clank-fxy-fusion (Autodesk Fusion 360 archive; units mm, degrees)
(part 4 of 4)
sketch "Y Belt Clamp" plane through (-23.5, 0, 0) normal (-1, 0, 0) x axis (0, -1, 0)
  line L1 (-13.5, 0) -> (-42.5, 0)
  line L2 (-13.5, 20) -> (-13.5, 0)
  line L3 (-42.5, 20) -> (-13.5, 20)
  line L4 (-42.5, 0) -> (-42.5, 20)
  line L5 (-37.5, 19.0415) -> (-34, 17.0207)
  line L6 (-41, 17.0207) -> (-37.5, 19.0415)
  line L7 (-41, 12.9793) -> (-41, 17.0207)
  line L8 (-37.5, 10.9585) -> (-41, 12.9793)
  line L9 (-34, 12.9793) -> (-37.5, 10.9585)
  line L10 (-34, 17.0207) -> (-34, 12.9793)
  line L11 (-23, 2.4793) -> (-23, 6.5207)
  line L12 (-16, 6.5207) -> (-16, 2.4793)
  line L13 (-16, 2.4793) -> (-19.5, 0.4585)
  line L14 (-23, 6.5207) -> (-19.5, 8.5415)
  line L15 (-19.5, 0.4585) -> (-23, 2.4793)
  line L16 (-19.5, 8.5415) -> (-16, 6.5207)
  line L17 (-72.1707, -2) -> (34.4892, -2)
  line L18 (-68.7635, -22) -> (35.0352, -22)
  line L19 (-16, -26.3293) -> (-16, -30.3707)
  line L20 (-23, -26.3293) -> (-19.5, -24.3085)
  line L21 (-19.5, -32.3915) -> (-23, -30.3707)
  line L22 (-16, -30.3707) -> (-19.5, -32.3915)
  line L23 (-23, -30.3707) -> (-23, -26.3293)
  line L24 (-19.5, -24.3085) -> (-16, -26.3293)
  line L25 (-19.5, -28.35) -> (-19.5, 4.5)
  line L26 (-25.5, -32.05) -> (-31, -32.05)
  line L27 (-25.5, -24.3085) -> (-25.5, -32.05)
  line L28 (-31, -24.3085) -> (-25.5, -24.3085)
  line L29 (-31, -32.05) -> (-31, -24.3085)
  line L30 (-12.5, -21.0085) -> (-12.5, -35.35)
  line L31 (-31, -21.0085) -> (-12.5, -21.0085)
  line L32 (-31, -20.0085) -> (-31, -21.0085)
  line L33 (-12.5, -20.0085) -> (-31, -20.0085)
  line L34 (-12.5, -0.2) -> (-12.5, -20.0085)
  line L35 (-55, -35.35) -> (-12.5, -35.35)
  line L36 (-12.5, -0.2) -> (-15.7704, -0.2)
  line L37 (-55, 26) -> (-55, -35.35)
  line L38 (-42.5, 26) -> (-55, 26)
  line L39 (-13.5, 26) -> (-13.5, 20)
  line L40 (-42.5, 26) -> (-13.5, 26)
  line L41 (-42.5, 26) -> (-42.5, 0)
  line L42 (-55, 0) -> (-42.5, 0)
  line L43 (-24.2, 26) -> (-24.2, 8.2296)
  line L44 (-55, 13.75) -> (-24.2, 13.75)
  line L45 (-49, 11.7915) -> (-45.5, 9.7707)
  line L46 (-52.5, 9.7707) -> (-49, 11.7915)
  line L47 (-52.5, 5.7293) -> (-52.5, 9.7707)
  line L48 (-49, 3.7085) -> (-52.5, 5.7293)
  line L49 (-45.5, 5.7293) -> (-49, 3.7085)
  line L50 (-45.5, 9.7707) -> (-45.5, 5.7293)
  line L51 (-14.1381, 0) -> (-13.5, 0)
  line L52 (-24, 9.8619) -> (-24, 8.4686)
  line L53 (-24.2, 11.5) -> (-19.5, 11.5)
  line L54 (-24.2, 10.5) -> (-19.5, 10.5)
  line L55 (-65, 13.75) -> (-55, 13.75)
  line L56 (-65, -35.35) -> (-65, 13.75)
  line L57 (-55, -35.35) -> (-65, -35.35)
  line L58 (-62.5, 5.7293) -> (-62.5, 9.7707)
  line L59 (-62.5, 9.7707) -> (-59, 11.7915)
  line L60 (-59, 3.7085) -> (-62.5, 5.7293)
  line L61 (-55.5, 9.7707) -> (-55.5, 5.7293)
  line L62 (-59, 11.7915) -> (-55.5, 9.7707)
  line L63 (-55.5, 5.7293) -> (-59, 3.7085)
  line L64 (-62.5, -31.3707) -> (-62.5, -27.3293)
  line L65 (-62.5, -27.3293) -> (-59, -25.3085)
  line L66 (-59, -33.3915) -> (-62.5, -31.3707)
  line L67 (-55.5, -27.3293) -> (-55.5, -31.3707)
  line L68 (-59, -25.3085) -> (-55.5, -27.3293)
  line L69 (-55.5, -31.3707) -> (-59, -33.3915)
  line L70 (-22, -16.0293) -> (-22, -11.9878)
  line L71 (-22, -11.9878) -> (-18.5, -9.9671)
  line L72 (-18.5, -18.05) -> (-22, -16.0293)
  line L73 (-15, -11.9878) -> (-15, -16.0293)
  line L74 (-18.5, -9.9671) -> (-15, -11.9878)
  line L75 (-15, -16.0293) -> (-18.5, -18.05)
  line L76 (-59, -29.35) -> (-59, 7.75)
  line L77 (-53, 1.75) -> (-53, 13.75)
  line L78 (-65, 1.75) -> (-53, 1.75)
  line L79 (-53, -23.35) -> (-65, -23.35)
  line L80 (-53, -35.35) -> (-53, -23.35)
  line L81 (-24.5, -8.0085) -> (-24.5, -20.0085)
  line L82 (-12.5, -8.0085) -> (-24.5, -8.0085)
  circle C1 centre (-37.5, 15) radius 2.125
  circle C2 centre (-37.5, 15) radius 4.25
  circle C3 centre (-19.5, 4.5) radius 4.75
  circle C4 centre (-19.5, 4.5) radius 2.125
  circle C5 centre (-19.5, 4.5) radius 6.5
  circle C6 centre (-19.5, 4.5) radius 7
  circle C7 centre (-19.5, -28.35) radius 2.125
  circle C8 centre (-19.5, -28.35) radius 6.5
  circle C9 centre (-19.5, 4.5) radius 6
  circle C10 centre (-49, 7.75) radius 2.125
  circle C11 centre (-49, 7.75) radius 4.5
  circle C12 centre (-59, 7.75) radius 2.125
  circle C13 centre (-59, -29.35) radius 2.125
  circle C14 centre (-18.5, -14.0085) radius 2.125
  point P6 (-37.5, 15)
  point P13 (-37.5, 15)
  point P14 (-37.5, 15)
  point P15 (-19.5, 4.5)
  point P20 (-19.5, 4.5)
  point P23 (-19.5, 4.5)
  point P29 (-19.5, 4.5)
  point P30 (-19.5, -28.35)
  point P36 (-19.5, -28.35)
  point P39 (-19.5, 4.5)
  point P40 (-19.5, -28.35)
  point P49 (-12.5, -20.0085)
  point P38 (-19.5, -28.35)
  point P44 (-31, -24.3085)
  point P50 (-12.5, -0.2)
  point P53 (-12.5, -0.2)
  point P55 (-42.5, 26)
  point P56 (-42.5, 26)
  point P4 (-13.5, 20)
  point P57 (-13.5, 20)
  point P59 (-42.5, 26)
  point P2 (-42.5, 0)
  point P60 (-42.5, 0)
  point P61 (-55, 0)
  point P62 (-19.5, 4.5)
  point P64 (-24.2, 26)
  point P63 (-24.2, 8.2296)
  point P66 (-24.2, 13.75)
  point P67 (-55, 13.75)
  point P69 (-49, 7.75)
  point P76 (-49, 7.75)
  point P52 (-15.7704, -0.2)
  point P3 (-13.5, 0)
  point P78 (-13.5, 0)
  point P79 (-14.1381, 0)
  point P80 (-24, 8.4686)
  point P81 (-24, 9.8619)
  point P68 (-24, 14.75)
  point P82 (-19.5, 11.5)
  point P83 (-24.2, 11.5)
  point P84 (-19.5, 10.5)
  point P85 (-24.2, 10.5)
  point P51 (-55, -35.35)
  point P88 (-55, -35.35)
  point P94 (-59, 7.75)
  point P96 (-59, 7.75)
  point P102 (-59, -29.35)
  point P104 (-59, -29.35)
  point P111 (-18.5, -14.0085)
  point P113 (-18.5, -14.0085)
  point P106 (-18.5, -14.0085)
  point P89 (-59, 7.75)
  point P115 (-59, 7.75)
  point P116 (-59, -29.35)
  point P117 (-53, 13.75)
  point P119 (-65, 1.75)
  point P120 (-65, -23.35)
  point P122 (-53, -35.35)
  point P118 (-53, 1.75)
  point P123 (-24.5, -20.0085)
  point P125 (-12.5, -8.0085)
  point P9 (-41, 17.0207)
  point P17 (-23, 6.5207)
  point P1 (0, 0)
  point P25 (-72.1707, -2)
  point P27 (-68.7635, -22)
  point P28 (-19.5, 4.5)
  point P32 (-23, -26.3293)
  point P35 (-19.5, -24.3085)
  point P41 (-31, -32.05)
  point P42 (-25.5, -32.05)
  point P47 (-31, -21.0085)
  point P48 (-31, -20.0085)
  point P65 (-24, 26)
  point P72 (-52.5, 9.7707)
  point P77 (-49, 7.75)
  point P87 (-65, -35.35)
  point P90 (-62.5, 9.7707)
  point P98 (-62.5, -27.3293)
  point P107 (-22, -11.9878)
  coincident P6 P13
  vertical L7
  coincident P13 P14
  coincident P15 P20
  vertical L11
  coincident P20 P23
  horizontal L17
  horizontal L18
  concentric C3 C5
  coincident P20 P29
  coincident P30 P36
  vertical L23
  coincident P15 P39
  coincident P36 P40
  vertical L25
  horizontal L26
  vertical L27
  horizontal L28
  vertical L29
  perpendicular L18 L30
  perpendicular L25 L31
  perpendicular L31 L32
  perpendicular L25 L33
  perpendicular L33 L34
  coincident L30 P49
  coincident P36 P38
  perpendicular L30 L35
  coincident P44 L32
  coincident P50 P53
  perpendicular L35 L37
  perpendicular L37 L38
  coincident P55 P56
  coincident P4 P57
  perpendicular L3 L39
  perpendicular L39 L40
  coincident P55 P59
  coincident P2 P60
  coincident L37 P61
  perpendicular L37 L42
  coincident P20 P62
  coincident L40 P64
  perpendicular L40 L43
  coincident C9 P63
  coincident L43 P66
  coincident L37 P67
  perpendicular L37 L44
  coincident P69 P76
  vertical L47
  concentric C10 C11
  coincident P52 C9
  horizontal L36
  coincident P3 P78
  perpendicular L2 L51
  coincident C6 P79
  coincident C9 P80
  coincident C6 P81
  vertical L52
  coincident P68 L52
  coincident C6 P82
  coincident L43 P83
  coincident C9 P84
  coincident L43 P85
  coincident L25 P84
  coincident L25 P82
  horizontal L53
  horizontal L54
  perpendicular L37 L55
  perpendicular L55 L56
  perpendicular L37 L57
  coincident P51 P88
  coincident P94 P96
  vertical L58
  coincident P102 P104
  vertical L64
  coincident P111 P113
  vertical L70
  coincident P106 P111
  coincident P89 P96
  coincident P89 P115
  coincident P102 P116
  vertical L76
  coincident L44 P117
  perpendicular L44 L77
  coincident L56 P119
  perpendicular L56 L78
  coincident L56 P120
  perpendicular L37 L79
  coincident L35 P122
  perpendicular L35 L80
  coincident P118 L80
  equal L77 L80
  coincident L33 P123
  perpendicular L33 L81
  coincident L34 P125
  perpendicular L34 L82
  equal L78 L81
  equal L81 L82
  dimension "d281" diameter C1 = 4.25
  dimension "d282" distance P9 L10 = 7 (= "hw_m4hex_d")
  dimension "d283" diameter C2 = 8.5
  dimension "d284" diameter C4 = 4.25
  dimension "d285" distance P17 L12 = 7 (= "hw_m4hex_d")
  dimension "d286" diameter C3 = 9.5
  dimension "d287" distance L3 P6 = 5
  dimension "d288" distance L4 P6 = 5
  dimension "d289" distance L2 P15 = 6
  dimension "d436" distance P1 L17 = 2
  dimension "d437" distance P25 P27 = 20 (= "extrusion_w")
  dimension "d438" diameter C5 = 13 (= "od_bearings")
  dimension "d439" distance L17 P28 = 6.5 (= "od_bearings / 2")
  dimension "d440" distance C5 C6 = 0.5
  dimension "d441" diameter C7 = 4.25
  dimension "d442" distance P32 L19 = 7 (= "hw_m4hex_d")
  dimension "d444" diameter C8 = 13 (= "od_bearings")
  dimension "d446" distance L18 P38 = 6.35 (= "od_bearings / 2 - preload")
  dimension "d455" distance P32 L27 = 2.5
  dimension "d457" distance P38 L30 = 7 (= "od_bearings / 2 + 0.5 mm")
  dimension "d458" distance P35 L31 = 3.3
  dimension "d459" distance L28 L31 = 3.3 (= "flex_t")
  dimension "d460" distance P38 L35 = 7 (= "od_bearings / 2 + 0.5 mm")
  dimension "d461" distance L26 L35 = 3.3 (= "flex_t")
  dimension "d462" distance P41 P42 = 5.5 (= "flex_l")
  dimension "d463" distance P47 P48 = 1
  dimension "d465" distance P1 L37 = 55
  dimension "d469" distance C6 C9 = 1
  dimension "d470" distance L43 P65 = 0.2
  dimension "d471" distance P66 P68 = 1
  dimension "d475" distance P72 L50 = 7 (= "hw_m4hex_d")
  dimension "d476" diameter C10 = 4.25
  dimension "d477" diameter C11 = 9
  dimension "d478" distance L44 P77 = 6
  dimension "d479" distance L37 P77 = 6
  dimension "d501" distance P3 L36 = 0.2
  dimension "d555" distance P87 P88 = 10
  dimension "d556" distance P90 L61 = 7 (= "hw_m4hex_d")
  dimension "d557" diameter C12 = 4.25
  dimension "d558" distance P98 L67 = 7 (= "hw_m4hex_d")
  dimension "d559" diameter C13 = 4.25
  dimension "d560" distance P107 L73 = 7 (= "hw_m4hex_d")
  dimension "d561" diameter C14 = 4.25
  dimension "d562" distance L34 P106 = 6
  dimension "d563" distance L33 P111 = 6
  dimension "d564" distance L56 P89 = 6
  dimension "d565" distance L55 P89 = 6
  dimension "d566" distance L57 P102 = 6
  dimension "d571" distance P96 L78 = 6
  dimension "d572" distance P89 L77 = 6
  dimension "d578" distance P94 P104 = 37.1
  dimension "d579" distance P102 P111 = 40.5
  dimension "d580" distance P104 P106 = 15.3415
extrude "Extrude27" cut sketch "Y Belt Clamp" profile of C1 C4 to an object
extrude "Extrude28" cut sketch "Y Belt Clamp" profile of C1 L5 L6 L7 L8 L9 L10 to an object from offset -19
chamfer "Chamfer9" distance 2.4
extrude "Extrude42" of existing geometry to an object from offset 11.5 (= "extrusion_w / 2 + 1.5 mm")
extrude "Extrude43" sketch "Y Belt Clamp" profile of L1 L2 L11 C3 L12 L13 C4 L14 L15 L16 C6 to an object offset 6.6 (= "t_bearings + ( 0.8 * 2 ) * 1 mm")
extrude "Extrude44" cut of existing geometry to an object
extrude "Extrude51" sketch "Y Belt Clamp" profile of L1 L2 C6 C9 L51 L52 L54 to an object
offset_faces "OffsetFaces4" distance -0.2
extrude "Extrude45" sketch "Y Belt Clamp" profile of L1 L4 C1 L7 L8 L9 L10 L11 C3 L12 L13 C4 L14 L15 L16 C6 L19 L20 L21 C7 L22 L23 L24 L26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 to an object from offset -0.1
extrude "Extrude46" sketch "Y Belt Clamp" profile of L4 L37 L41 L42 L44 C10 L45 L46 L47 L48 L49 L50 to an object
extrude "Extrude47" sketch "Y Belt Clamp" profile of L11 L12 L13 C4 L14 L15 L16 L19 L20 L21 C7 L22 L23 L24 C10 L45 L46 L47 L48 L49 L50 to an object from offset -2.5
extrude "Extrude48" sketch "Y Belt Clamp" profile of L1 L11 C3 L12 L13 C4 L14 L15 L16 to an object from offset 34
chamfer "Chamfer16" distance 2.625 (= "( ( 9.5 - 4.25 ) / 2 ) * 1 mm")
fillet "Fillet18" radius 1
extrude "Extrude49" sketch "Y Belt Clamp" profile of C10 L45 L46 L47 L48 L49 L50 C11 to an object from offset 19
chamfer "Chamfer17" distance 2.375 (= "( ( 9 - 4.25 ) / 2 ) * 1 mm")
extrude "Extrude50" add of existing geometry to an object
extrude "Extrude59" sketch "Y Belt Clamp" profile of C12 L58 L59 L60 L61 L62 L63 C13 L64 L65 L66 L67 L68 L69 C14 L70 L71 L72 L73 L74 L75 blind -8
chamfer "Chamfer23" distance 1.7
extrude "Extrude60" sketch "Y Belt Clamp" profile of L33 L34 L35 L37 L44 C11 L55 L56 L57 C12 L58 L59 L60 L61 L62 L63 C13 L64 L65 L66 L67 L68 L69 C14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 blind -1
extrude "Extrude52" add of existing geometry blind 7.2
sketch "Y Limit Touch" plane through (0, 0, 26) normal (0, 0, 1) x axis (-1, 0, 0)
  line L1 (-30.05, 24) -> (-19.9664, 24)
  line L2 (-30.05, -24) -> (-30.05, 24)
  line L3 (-19.9664, -24) -> (-30.05, -24)
  line L4 (-19.9664, 24) -> (-19.9664, -24)
  line L5 (-24.35, 24) -> (-24.35, -24)
  line L6 (-23.35, -10.075) -> (-23.35, -24)
  point P6 (-24.35, -24)
  point P7 (-24.35, 24)
  coincident L3 P6
  coincident L1 P7
  perpendicular L1 L5
  dimension "d520" distance P6 L6 = 1
extrude "Extrude53" add sketch "Y Limit Touch" profile of L1 L2 L3 L5 along normal blind 9
fillet "Fillet27" radius 2
sketch "Y Travel Stop" plane through (0, 0, 26) normal (0, 0, 1) x axis (-1, 0, 0)
  line L1 (21.0151, -2.465) -> (18.7576, 1.4452)
  line L2 (18.7576, -6.3752) -> (21.0151, -2.465)
  line L3 (14.2424, -6.3752) -> (18.7576, -6.3752)
  line L4 (11.9849, -2.465) -> (14.2424, -6.3752)
  line L5 (14.2424, 1.4452) -> (11.9849, -2.465)
  line L6 (18.7576, 1.4452) -> (14.2424, 1.4452)
  line L7 (-18.325, -10.075) -> (10.075, -10.075)
  line L8 (-18.325, -24) -> (-18.325, -10.075)
  line L9 (-11.5, -24) -> (-18.325, -24)
  line L10 (-11.5, -55) -> (-11.5, -24)
  line L11 (11.65, -55) -> (-11.5, -55)
  line L12 (11.65, -12.5) -> (11.65, -55)
  line L13 (23.5, -12.5) -> (11.65, -12.5)
  line L14 (23.5, 12.5) -> (23.5, -12.5)
  line L15 (11.65, 12.5) -> (23.5, 12.5)
  line L16 (11.65, 30) -> (11.65, 12.5)
  line L17 (-10.075, 30) -> (11.65, 30)
  line L18 (-10.075, 24) -> (-10.075, 30)
  line L19 (-18.325, 24) -> (-10.075, 24)
  line L20 (-18.325, 10.075) -> (-18.325, 24)
  line L21 (10.075, 10.075) -> (-18.325, 10.075)
  line L22 (10.075, -10.075) -> (10.075, 10.075)
  line L23 (10.075, -24) -> (10.075, -10.075)
  line L24 (-18.325, -24) -> (10.075, -24)
  line L25 (-18.325, -10.075) -> (-18.325, -24)
  line L26 (10.075, 24) -> (10.075, 10.075)
  line L27 (-18.325, 24) -> (10.075, 24)
  line L28 (-18.325, 10.075) -> (-18.325, 24)
  line L29 (-12.35, -10.075) -> (-12.35, -24)
  line L30 (-12.35, 24) -> (-12.35, 10.075)
  point P8 (10.075, -10.075)
  point P24 (10.075, -10.075)
  point P27 (-18.325, -10.075)
  point P23 (10.075, 10.075)
  point P28 (10.075, 10.075)
  point P31 (-18.325, 10.075)
  point P9 (-18.325, -10.075)
  point P20 (-10.075, 24)
  point P11 (-11.5, -24)
  point P32 (-12.35, -24)
  point P33 (-12.35, -10.075)
  point P34 (-12.35, 10.075)
  point P35 (-12.35, 24)
  point P36 (-23.35, -24)
  coincident P8 P24
  perpendicular L7 L23
  perpendicular L23 L24
  coincident L7 P27
  perpendicular L24 L25
  coincident P23 P28
  perpendicular L21 L26
  perpendicular L22 L27
  coincident L21 P31
  perpendicular L21 L28
  coincident P27 L28
  coincident P9 P27
  coincident P20 L27
  coincident P11 L24
  coincident L24 P32
  coincident L7 P33
  perpendicular L7 L29
  coincident L21 P34
  perpendicular L27 L30
  coincident L27 P35
  coincident L29 P34
  dimension "d547" distance L29 P36 = 11
extrude "Extrude54" add sketch "Y Travel Stop" profile of L7 L21 L23 L24 L25 L26 L27 L28 along normal blind 8
extrude "Extrude58" sketch "Y Travel Stop" profile of L7 L8 L9 L19 L20 L21 L24 L25 L27 L28 L29 L30 to an object from offset 15
chamfer "Chamfer20" distance 1
chamfer "Chamfer21" distance 3
fillet "Fillet28" radius 2
extrude "Extrude55" add of existing geometry blind 10
sketch "Lower Tram Trim" plane through (-23.5, 0, 0) normal (-1, 0, 0) x axis (0, -1, 0)
  line L1 (30, 0) -> (-13.3, 0)
  line L2 (30, 14.75) -> (30, 0)
  line L3 (12.5, 14.75) -> (30, 14.75)
  line L4 (12.5, 26) -> (12.5, 14.75)
  line L5 (-12.5, 26) -> (12.5, 26)
  line L6 (-12.5, 14.75) -> (-12.5, 26)
  line L7 (-13.3, 14.75) -> (-12.5, 14.75)
  line L8 (-13.3, 0) -> (-13.3, 14.75)
  line L9 (30, 4) -> (26, 0)
  point P10 (26, 0)
  point P11 (30, 4)
  point P3 (30, 0)
  coincident L1 P10
  coincident L2 P11
  dimension "d536" angle L1 L9 = 45
  dimension "d546" distance P3 P10 = 4
extrude "Extrude56" cut sketch "Lower Tram Trim" profile of L1 L2 L9 to an object
sketch "Upper Tram Trim" plane through (-11.65, 0, 0) normal (-1, 0, 0) x axis (0, -1, 0)
  line L1 (-16, 16.4585) -> (-12.5, 18.4793)
  line L2 (-19.5, 18.4793) -> (-16, 16.4585)
  line L3 (-19.5, 22.5207) -> (-19.5, 18.4793)
  line L4 (-16, 24.5415) -> (-19.5, 22.5207)
  line L5 (-12.5, 22.5207) -> (-16, 24.5415)
  line L6 (-12.5, 26) -> (-12.5, 22.5207)
  line L7 (-65, 26) -> (-12.5, 26)
  line L8 (-65, 0) -> (-65, 26)
  line L9 (-13.3, 0) -> (-65, 0)
  line L10 (-13.3, 14.75) -> (-13.3, 0)
  line L11 (-12.5, 14.75) -> (-13.3, 14.75)
  line L12 (-12.5, 18.4793) -> (-12.5, 14.75)
  line L13 (-61, 0) -> (-65, 4)
  circle C1 centre (-49, 7.75) radius 4.5
  circle C2 centre (-19.5, 4.5) radius 2.125
  circle C3 centre (-37.5, 15) radius 2.125
  point P18 (-61, 0)
  point P17 (-65, 4)
  point P13 (-65, 0)
  coincident L9 P18
  coincident L8 P17
  dimension "d540" angle L9 L13 = 45
  dimension "d545" distance P13 P18 = 4
extrude "Extrude57" cut sketch "Upper Tram Trim" profile of L8 L9 L13 to an object
chamfer "Chamfer18" distance 1
fillet "Fillet22" radius 1
fillet "Fillet23" radius 1
fillet "Fillet24" radius 1.2
fillet "Fillet25" radius 0.5
fillet "Fillet26" radius 0.5
fillet "Fillet29" radius 1
component_insert "Component Insert3"
joint "Assemble3" alignAngle 0 alignOffsetX 0 alignOffsetY 0 alignOffsetZ 0
component_insert "Component Insert4"
joint "Assemble4" alignAngle 0 alignOffsetX 0 alignOffsetY 0 alignOffsetZ 0
component_insert "Component Insert1"
joint "Assemble1" alignAngle 180 alignOffsetX 0 alignOffsetY 0 alignOffsetZ 0
component_insert "Component Insert2"
joint "Assemble2" alignAngle 180 alignOffsetX 0 alignOffsetY 0 alignOffsetZ 0
component_insert "Component Insert5"
joint "Assemble5" alignAngle 180 alignOffsetX 0 alignOffsetY 0 alignOffsetZ 0
component_insert "Component Insert7"
component_insert "Component Insert8"
component_insert "Component Insert9"
component_insert "Component Insert10"
component_insert "Component Insert11"
component_insert "Component Insert12"
component_insert "Component Insert13"
component_insert "Component Insert14"
component_insert "Component Insert15"
component_insert "Component Insert16"
component_insert "Component Insert17"
joint "Assemble7" alignAngle 30 alignOffsetX 0 alignOffsetY 0 alignOffsetZ -1.5
joint "Assemble8" alignAngle 30 alignOffsetX 0 alignOffsetY 0 alignOffsetZ -1.5
joint "Assemble9" alignAngle 30 alignOffsetX 0 alignOffsetY 0 alignOffsetZ -1.5
joint "Assemble10" alignAngle 30 alignOffsetX 0 alignOffsetY 0 alignOffsetZ 0
joint "Assemble11" alignAngle 30 alignOffsetX 0 alignOffsetY 0 alignOffsetZ 0
joint "Assemble12" alignAngle 30 alignOffsetX 0 alignOffsetY 0 alignOffsetZ 0
joint "Assemble13" alignAngle 30 alignOffsetX 0 alignOffsetY 0 alignOffsetZ 0
joint "Assemble14" alignAngle 30 alignOffsetX 0 alignOffsetY 0 alignOffsetZ 0
joint "Assemble15" alignAngle 30 alignOffsetX 0 alignOffsetY 0 alignOffsetZ 0
joint "Assemble16" alignAngle 30 alignOffsetX 0 alignOffsetY 0 alignOffsetZ 0
joint "Assemble17" alignAngle 30 alignOffsetX 0 alignOffsetY 0 alignOffsetZ 0
component_insert "Component Insert18"
component_insert "Component Insert19"
joint "Assemble18" alignAngle 180 alignOffsetX 0 alignOffsetY 0 alignOffsetZ 0
joint "Assemble19" alignAngle 180 alignOffsetX 0 alignOffsetY 0 alignOffsetZ 0
component_insert "Component Insert23"
component_insert "Component Insert24"
joint "Assemble20" alignAngle 180 alignOffsetX 0 alignOffsetY 0 alignOffsetZ 0
joint "Assemble21" alignAngle 180 alignOffsetX 0 alignOffsetY 0 alignOffsetZ 0
component_insert "Component Insert25"
joint "Assemble22" alignAngle 180 alignOffsetX 0 alignOffsetY 0 alignOffsetZ 0
component_insert "Component Insert26"
component_insert "Component Insert27"
component_insert "Component Insert29"
joint "Assemble23" alignAngle 0 alignOffsetX 0 alignOffsetY 0 alignOffsetZ 0
joint "Assemble24" alignAngle 0 alignOffsetX 0 alignOffsetY 0 alignOffsetZ 0
joint "Assemble25" alignAngle 0 alignOffsetX 0 alignOffsetY 0 alignOffsetZ 0
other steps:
joint_origin "JointOrigin9"
joint_origin "JointOrigin11"
joint_origin "JointOrigin12"
joint_origin "JointOrigin13"
joint_origin "JointOrigin14"
joint_origin "JointOrigin15"
joint_origin "JointOrigin16"
joint_origin "JointOrigin17"
joint_origin "JointOrigin18"
joint_origin "JointOrigin19"
joint_origin "JointOrigin20"
joint_origin "JointOrigin21"
joint_origin "JointOrigin22"
joint_origin "JointOrigin23"
joint_origin "JointOrigin24"
joint_origin "JointOrigin25"
joint_origin "JointOrigin26"
joint_origin "JointOrigin27"
joint_origin "JointOrigin28"
joint_origin "JointOrigin29"
joint_origin "JointOrigin30"
named bodies: "YLB", "YLB Z Belt Clamp", "YLF Y Belt Clamp", "YLF Y Constraint"

design "HW_M4-Washer"
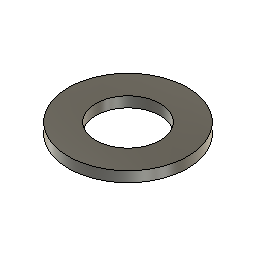
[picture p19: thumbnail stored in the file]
sketch "Sketch1" plane through (0, 0, 0) normal (0, 1, 0) x axis (1, 0, 0)
  line L1 (4, 0) -> (2.15, 0)
  line L2 (4, -0.7) -> (4, 0)
  line L3 (2.15, -0.7) -> (4, -0.7)
  line L4 (2.15, 0) -> (2.15, -0.7)
  point P1 (0, 0)
  point P2 (2.15, 0)
  point P5 (2.15, -0.7)
  horizontal L1
  vertical L2
  horizontal L3
  vertical L4
  coincident P1 L1
  dimension "d1" distance P2 P5 = 0.7
  dimension "d2" distance P1 L4 = 2.15 (= "( 4.3 / 2 ) * 1 mm")
  dimension "d3" distance P1 L2 = 4 (= "( 8 / 2 ) * 1 mm")
revolve "Revolve1" sketch "Sketch1" AlongAngle 360

design "Bus 3010 Terminal Mount" references "CT_UCBus-3010"
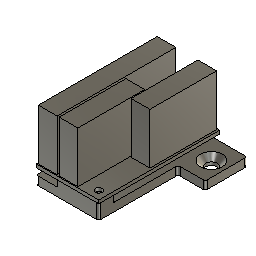
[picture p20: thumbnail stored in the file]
sketch "Sketch1" plane through (0, 0, 0) normal (0, 0, 1) x axis (1, 0, 0)
  line L1 (30, 0) -> (0, 0)
  line L2 (30, 58) -> (30, 0)
  line L3 (0, 0) -> (0, 58)
  line L4 (0, 58) -> (30, 58)
  line L5 (24, 50) -> (24, 58)
  line L6 (4, 50) -> (24, 50)
  line L7 (4, 58) -> (4, 50)
  line L8 (10, 8) -> (10, 0)
  line L9 (30, 8) -> (10, 8)
  line L10 (14, 50) -> (14, 54)
  line L11 (43, 58) -> (30, 58)
  line L12 (43, 38) -> (43, 58)
  line L13 (30, 38) -> (43, 38)
  line L14 (-13, 38) -> (0, 38)
  line L15 (-13, 58) -> (-13, 38)
  line L16 (0, 58) -> (-13, 58)
  line L17 (36, 48) -> (43, 48)
  line L18 (-6, 48) -> (-13, 48)
  circle C1 centre (14, 54) radius 1.35
  circle C2 centre (26, 4) radius 1.35
  circle C3 centre (36, 48) radius 2.75
  circle C4 centre (-6, 48) radius 2.75
  circle C5 centre (36, 48) radius 5
  point P1 (0, 0)
  point P2 (0, 0)
  point P8 (24, 58)
  point P11 (4, 58)
  point P12 (10, 0)
  point P14 (30, 8)
  point P6 (14, 54)
  point P15 (14, 54)
  point P16 (14, 50)
  point P19 (30, 38)
  point P20 (0, 38)
  point P5 (0, 58)
  point P23 (0, 58)
  point P24 (43, 48)
  point P25 (36, 48)
  point P26 (36, 48)
  point P27 (-13, 48)
  point P28 (-6, 48)
  point P29 (-6, 48)
  point P4 (30, 58)
  point P7 (26, 4)
  point P13 (10, 8)
  point P9 (24, 50)
  point P10 (4, 50)
  point P17 (43, 58)
  point P18 (43, 38)
  point P30 (36, 48)
  horizontal L1
  vertical L2
  horizontal L4
  vertical L3
  coincident P1 P2
  equal C1 C2
  coincident L4 P8
  perpendicular L4 L5
  perpendicular L5 L6
  coincident L4 P11
  perpendicular L4 L7
  coincident L1 P12
  perpendicular L1 L8
  coincident L2 P14
  perpendicular L2 L9
  coincident P6 P15
  midpoint L6 P16
  vertical L10
  perpendicular L2 L11
  perpendicular L11 L12
  coincident L2 P19
  perpendicular L2 L13
  coincident L3 P20
  perpendicular L3 L14
  perpendicular L14 L15
  perpendicular L15 L16
  coincident P5 P23
  midpoint L12 P24
  perpendicular L12 L17
  coincident P25 P26
  midpoint L15 P27
  perpendicular L15 L18
  coincident P28 P29
  concentric C3 C5
  equal C3 C4
  equal L13 L14
  coincident L13 P20
  equal L17 L18
  dimension "d1" distance P4 P5 = 30
  dimension "d2" distance P2 P5 = 58
  dimension "d3" distance P6 L4 = 4
  dimension "d6" diameter C1 = 2.7
  dimension "d7" distance L3 P6 = 14
  dimension "d25" distance L1 P7 = 4
  dimension "d48" distance L2 P7 = 4
  dimension "d51" distance P7 L9 = 4
  dimension "d52" distance P13 P14 = 20
  dimension "d53" distance P9 P10 = 20
  dimension "d54" distance P8 P9 = 8
  dimension "d55" diameter C5 = 10
  dimension "d56" diameter C3 = 5.5
  dimension "d57" distance P17 P18 = 20
  dimension "d59" distance P24 P25 = 7
  dimension "d60" distance P4 P30 = 6
extrude "Extrude1" new body sketch "Sketch1" profile of L1 L2 L4 L3 C1 C2 L5 L6 L7 L8 L9 L11 L12 L13 L14 L15 L16 C3 C4 along normal blind 4
extrude "Extrude4" sketch "Sketch1" profile of L1 L2 L4 C1 C2 L5 L6 L7 L8 L9 blind 3
chamfer "Chamfer1" distance 2.5
fillet "Fillet1" radius 1
component_insert "Component Insert"
joint "Assemble1" alignAngle 0 alignOffsetX 0 alignOffsetY 0 alignOffsetZ 0
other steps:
joint_origin "JointOrigin1"

design "M6 Lock Washer 95060A360"
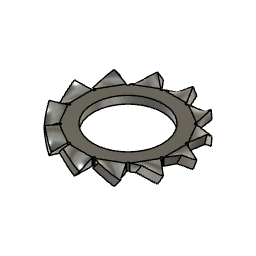
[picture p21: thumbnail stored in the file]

design "HW_M5x25-FHCS"
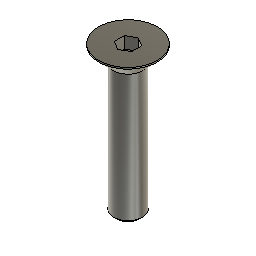
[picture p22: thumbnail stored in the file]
sketch "Sketch1" plane through (0, 0, 0) normal (0, 1, 0) x axis (1, 0, 0)
  line L1 (0, 25) -> (0, 0)
  line L2 (1.95, 25) -> (0, 25)
  line L3 (2.45, 24.5) -> (1.95, 25)
  line L4 (2.45, 2.8) -> (2.45, 24.5)
  line L5 (5, 0.25) -> (2.45, 2.8)
  line L6 (5, 0) -> (5, 0.25)
  line L7 (0, 0) -> (5, 0)
  point P1 (0, 0)
  point P2 (0, 0)
  point P9 (0, 0)
  point P3 (0, 25)
  point P4 (1.95, 25)
  point P8 (5, 0)
  point P7 (5, 0.25)
  coincident P1 P2
  vertical L1
  perpendicular L1 L2
  perpendicular L2 L4
  parallel L3 L5
  parallel L4 L6
  perpendicular L6 L7
  coincident P1 P9
  dimension "d1" distance P3 L4 = 2.45 (= "( 4.9 / 2 ) * 1 mm")
  dimension "d3" angle L2 L3 = 45
  dimension "d5" distance P4 L4 = 0.5
  dimension "d6" distance P2 P3 = 25
  dimension "d7" distance P8 P9 = 5 (= "( 10 / 2 ) * 1 mm")
  dimension "d9" distance P7 P8 = 0.25
revolve "Revolve1" sketch "Sketch1" AlongAngle 360
sketch "Sketch2" plane through (0, 0, 0) normal (0, 0, 1) x axis (-1, 0, 0)
  line L1 (0, -1.7321) -> (-1.5, -0.866)
  line L2 (1.5, -0.866) -> (0, -1.7321)
  line L3 (1.5, 0.866) -> (1.5, -0.866)
  line L4 (0, 1.7321) -> (1.5, 0.866)
  line L5 (-1.5, 0.866) -> (0, 1.7321)
  line L6 (-1.5, -0.866) -> (-1.5, 0.866)
  circle C1 centre (0, 0) radius 5
  point P1 (0, 0)
  point P9 (0, 0)
  coincident P1 P9
  vertical L6
  dimension "d12" distance L3 L6 = 3
extrude "Extrude1" cut sketch "Sketch2" profile of L1 L2 L3 L4 L5 L6 against normal blind 2

design "PP_FOOD_Banana-For-Scale"
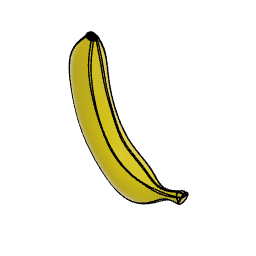
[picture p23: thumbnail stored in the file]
